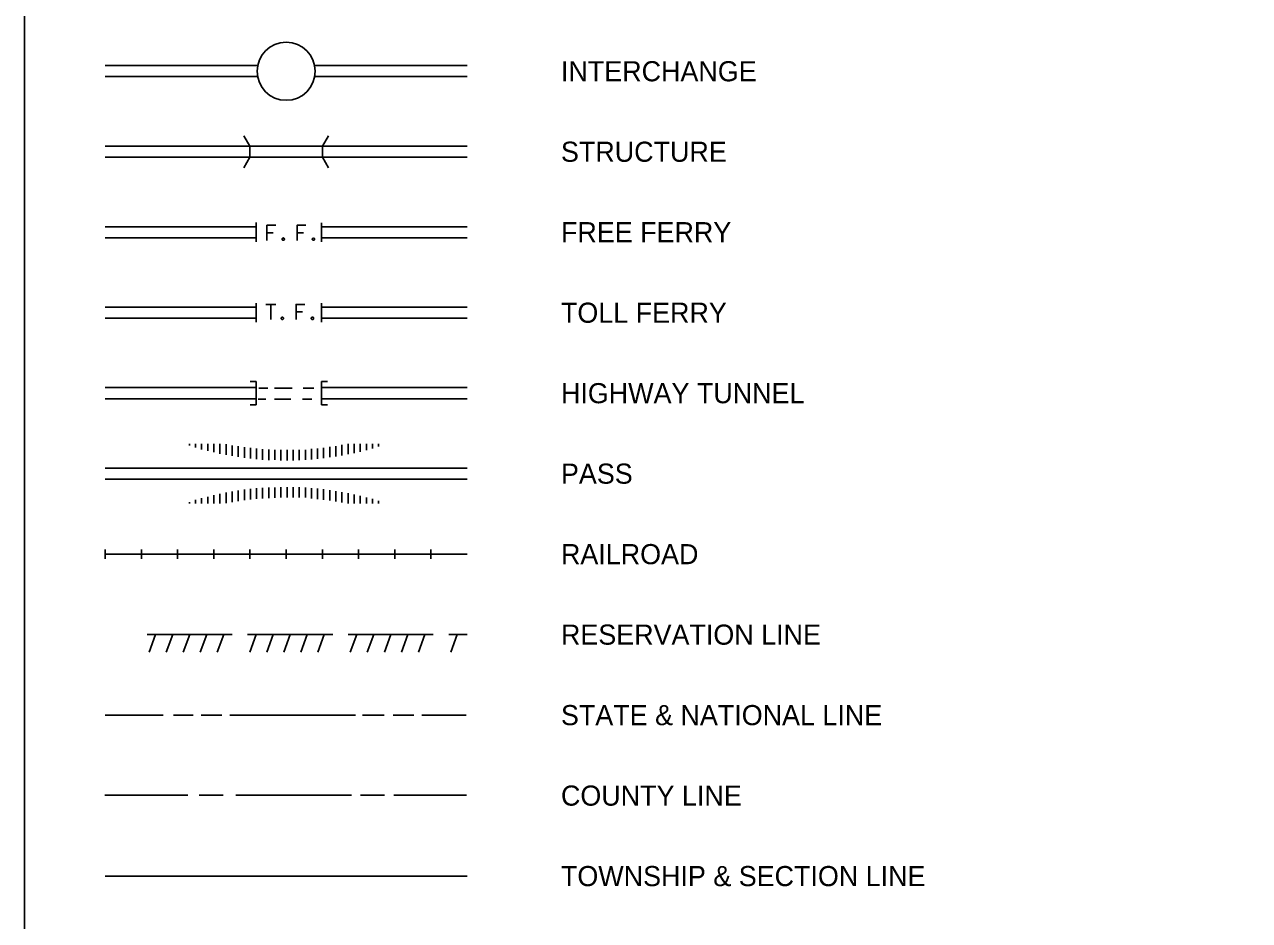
# Model space of a CAD drawing. Extents: x 49991.4 to 50021, y 49987.6 to 50011.4.
# Drawn here: x 49999.384 to 50003.039, y 49993.483 to 49996.155 of the extents above; entities that cross this region are included whole.
import ezdxf

# ---------------------------------------------------------------- set-up
doc = ezdxf.new("R2010")
doc.units = 0
doc.layers.add('Level 1', color=7, linetype='Continuous')
doc.layers.add('Level 2', color=7, linetype='Continuous')

msp = doc.modelspace()

# ---------------------------------------------------------------- linework, layer by layer
at = {"layer": 'Level 1'}
for p, q in [((49999.6243, 49996.0324), (50000.0793, 49996.0324)), ((50000.249, 49996.0324), (50000.7043, 49996.0324)), ((49999.6243, 49995.9994), (50000.0788, 49995.9994)), ((50000.2495, 49995.9994), (50000.7043, 49995.9994)), ((50000.0563, 49995.7917), (50000.0383, 49995.8228)), ((50000.2723, 49995.7917), (50000.2903, 49995.8228)), ((49999.6243, 49995.7917), (50000.7043, 49995.7917)), ((50000.0563, 49995.7917), (50000.0563, 49995.7587)), ((50000.2723, 49995.7917), (50000.2723, 49995.7587)), ((49999.6243, 49995.7587), (50000.7043, 49995.7587)), ((50000.0563, 49995.7587), (50000.0383, 49995.7275)), ((50000.2723, 49995.7587), (50000.2903, 49995.7275)), ((49999.6243, 49995.5517), (50000.0745, 49995.5517)), ((50000.0744, 49995.5067), (50000.0744, 49995.564)), ((50000.2697, 49995.5067), (50000.2697, 49995.5636)), ((50000.2698, 49995.5517), (50000.7043, 49995.5517)), ((49999.6243, 49995.5187), (50000.0745, 49995.5187)), ((50000.1075, 49995.5335), (50000.1259, 49995.5335)), ((50000.1523, 49995.5152), (50000.1522, 49995.5148)), ((50000.1522, 49995.5148), (50000.1522, 49995.5145)), ((50000.1522, 49995.5145), (50000.1522, 49995.5141)), ((50000.1522, 49995.5141), (50000.1523, 49995.5137)), ((50000.1524, 49995.5156), (50000.1523, 49995.5152)), ((50000.1523, 49995.5137), (50000.1524, 49995.5134)), ((50000.1525, 49995.5159), (50000.1524, 49995.5156)), ((50000.1524, 49995.5134), (50000.1525, 49995.513)), ((50000.1527, 49995.5162), (50000.1525, 49995.5159)), ((50000.1525, 49995.513), (50000.1527, 49995.5127)), ((50000.1529, 49995.5166), (50000.1527, 49995.5162)), ((50000.1527, 49995.5127), (50000.1529, 49995.5124)), ((50000.1531, 49995.5168), (50000.1529, 49995.5166)), ((50000.1529, 49995.5124), (50000.1531, 49995.5121)), ((50000.1534, 49995.5171), (50000.1531, 49995.5168)), ((50000.1531, 49995.5121), (50000.1534, 49995.5118)), ((50000.1536, 49995.5173), (50000.1534, 49995.5171)), ((50000.1534, 49995.5118), (50000.1536, 49995.5116)), ((50000.154, 49995.5175), (50000.1536, 49995.5173)), ((50000.1536, 49995.5116), (50000.154, 49995.5114)), ((50000.1543, 49995.5177), (50000.154, 49995.5175)), ((50000.154, 49995.5114), (50000.1543, 49995.5112)), ((50000.1546, 49995.5178), (50000.1543, 49995.5177)), ((50000.1543, 49995.5112), (50000.1546, 49995.5111)), ((50000.155, 49995.5179), (50000.1546, 49995.5178)), ((50000.1546, 49995.5111), (50000.155, 49995.511)), ((50000.1554, 49995.518), (50000.155, 49995.5179)), ((50000.155, 49995.511), (50000.1554, 49995.511)), ((50000.1557, 49995.518), (50000.1554, 49995.518)), ((50000.1554, 49995.511), (50000.1557, 49995.5109)), ((50000.1561, 49995.518), (50000.1557, 49995.518)), ((50000.1557, 49995.5109), (50000.1561, 49995.511)), ((50000.1565, 49995.5179), (50000.1561, 49995.518)), ((50000.1561, 49995.511), (50000.1565, 49995.511)), ((50000.1568, 49995.5178), (50000.1565, 49995.5179)), ((50000.1565, 49995.511), (50000.1568, 49995.5111)), ((50000.1572, 49995.5177), (50000.1568, 49995.5178)), ((50000.1568, 49995.5111), (50000.1572, 49995.5112)), ((50000.1575, 49995.5175), (50000.1572, 49995.5177)), ((50000.1572, 49995.5112), (50000.1575, 49995.5114)), ((50000.1578, 49995.5173), (50000.1575, 49995.5175)), ((50000.1575, 49995.5114), (50000.1578, 49995.5116)), ((50000.1581, 49995.5171), (50000.1578, 49995.5173)), ((50000.1578, 49995.5116), (50000.1581, 49995.5118)), ((50000.1584, 49995.5168), (50000.1581, 49995.5171)), ((50000.1581, 49995.5118), (50000.1584, 49995.5121)), ((50000.1586, 49995.5166), (50000.1584, 49995.5168)), ((50000.1584, 49995.5121), (50000.1586, 49995.5124)), ((50000.1588, 49995.5162), (50000.1586, 49995.5166)), ((50000.1586, 49995.5124), (50000.1588, 49995.5127)), ((50000.159, 49995.5159), (50000.1588, 49995.5162)), ((50000.1588, 49995.5127), (50000.159, 49995.513)), ((50000.1591, 49995.5156), (50000.159, 49995.5159)), ((50000.159, 49995.513), (50000.1591, 49995.5134)), ((50000.1592, 49995.5152), (50000.1591, 49995.5156)), ((50000.1591, 49995.5134), (50000.1592, 49995.5137)), ((50000.1593, 49995.5148), (50000.1592, 49995.5152)), ((50000.1592, 49995.5137), (50000.1593, 49995.5141)), ((50000.1593, 49995.5145), (50000.1593, 49995.5148)), ((50000.1593, 49995.5141), (50000.1593, 49995.5145)), ((50000.1975, 49995.5335), (50000.2159, 49995.5335)), ((50000.2423, 49995.5152), (50000.2422, 49995.5148)), ((50000.2422, 49995.5148), (50000.2422, 49995.5145)), ((50000.2422, 49995.5145), (50000.2422, 49995.5141)), ((50000.2422, 49995.5141), (50000.2423, 49995.5137)), ((50000.2424, 49995.5156), (50000.2423, 49995.5152)), ((50000.2423, 49995.5137), (50000.2424, 49995.5134)), ((50000.2425, 49995.5159), (50000.2424, 49995.5156)), ((50000.2424, 49995.5134), (50000.2425, 49995.513)), ((50000.2427, 49995.5162), (50000.2425, 49995.5159)), ((50000.2425, 49995.513), (50000.2427, 49995.5127)), ((50000.2429, 49995.5166), (50000.2427, 49995.5162)), ((50000.2427, 49995.5127), (50000.2429, 49995.5124)), ((50000.2431, 49995.5168), (50000.2429, 49995.5166)), ((50000.2429, 49995.5124), (50000.2431, 49995.5121)), ((50000.2434, 49995.5171), (50000.2431, 49995.5168)), ((50000.2431, 49995.5121), (50000.2434, 49995.5118)), ((50000.2436, 49995.5173), (50000.2434, 49995.5171)), ((50000.2434, 49995.5118), (50000.2436, 49995.5116)), ((50000.244, 49995.5175), (50000.2436, 49995.5173)), ((50000.2436, 49995.5116), (50000.244, 49995.5114)), ((50000.2443, 49995.5177), (50000.244, 49995.5175)), ((50000.244, 49995.5114), (50000.2443, 49995.5112)), ((50000.2446, 49995.5178), (50000.2443, 49995.5177)), ((50000.2443, 49995.5112), (50000.2446, 49995.5111)), ((50000.245, 49995.5179), (50000.2446, 49995.5178)), ((50000.2446, 49995.5111), (50000.245, 49995.511)), ((50000.2454, 49995.518), (50000.245, 49995.5179)), ((50000.245, 49995.511), (50000.2454, 49995.511)), ((50000.2457, 49995.518), (50000.2454, 49995.518)), ((50000.2454, 49995.511), (50000.2457, 49995.5109)), ((50000.2461, 49995.518), (50000.2457, 49995.518)), ((50000.2457, 49995.5109), (50000.2461, 49995.511)), ((50000.2465, 49995.5179), (50000.2461, 49995.518)), ((50000.2461, 49995.511), (50000.2465, 49995.511)), ((50000.2468, 49995.5178), (50000.2465, 49995.5179)), ((50000.2465, 49995.511), (50000.2468, 49995.5111)), ((50000.2472, 49995.5177), (50000.2468, 49995.5178)), ((50000.2468, 49995.5111), (50000.2472, 49995.5112)), ((50000.2475, 49995.5175), (50000.2472, 49995.5177)), ((50000.2472, 49995.5112), (50000.2475, 49995.5114)), ((50000.2478, 49995.5173), (50000.2475, 49995.5175)), ((50000.2475, 49995.5114), (50000.2478, 49995.5116)), ((50000.2481, 49995.5171), (50000.2478, 49995.5173)), ((50000.2478, 49995.5116), (50000.2481, 49995.5118)), ((50000.2484, 49995.5168), (50000.2481, 49995.5171)), ((50000.2481, 49995.5118), (50000.2484, 49995.5121)), ((50000.2486, 49995.5166), (50000.2484, 49995.5168)), ((50000.2484, 49995.5121), (50000.2486, 49995.5124)), ((50000.2488, 49995.5162), (50000.2486, 49995.5166)), ((50000.2486, 49995.5124), (50000.2488, 49995.5127)), ((50000.249, 49995.5159), (50000.2488, 49995.5162)), ((50000.2488, 49995.5127), (50000.249, 49995.513)), ((50000.2491, 49995.5156), (50000.249, 49995.5159)), ((50000.249, 49995.513), (50000.2491, 49995.5134)), ((50000.2492, 49995.5152), (50000.2491, 49995.5156)), ((50000.2491, 49995.5134), (50000.2492, 49995.5137)), ((50000.2493, 49995.5148), (50000.2492, 49995.5152)), ((50000.2492, 49995.5137), (50000.2493, 49995.5141)), ((50000.2493, 49995.5145), (50000.2493, 49995.5148)), ((50000.2493, 49995.5141), (50000.2493, 49995.5145)), ((50000.27, 49995.5187), (50000.7043, 49995.5187)), ((50000.0743, 49995.3237), (50000.0743, 49995.267)), ((50000.27, 49995.3237), (50000.27, 49995.2667)), ((49999.6243, 49995.3117), (50000.0745, 49995.3117)), ((50000.1041, 49995.3197), (50000.1335, 49995.3197)), ((50000.119, 49995.3197), (50000.119, 49995.2747)), ((50000.1945, 49995.2974), (50000.2129, 49995.2974)), ((50000.27, 49995.3117), (50000.7043, 49995.3117)), ((49999.6243, 49995.2787), (50000.0745, 49995.2787)), ((50000.1493, 49995.2791), (50000.1492, 49995.2787)), ((50000.1492, 49995.2787), (50000.1492, 49995.2784)), ((50000.1492, 49995.2784), (50000.1492, 49995.278)), ((50000.1492, 49995.278), (50000.1493, 49995.2776)), ((50000.1494, 49995.2795), (50000.1493, 49995.2791)), ((50000.1493, 49995.2776), (50000.1494, 49995.2773)), ((50000.1495, 49995.2798), (50000.1494, 49995.2795)), ((50000.1494, 49995.2773), (50000.1495, 49995.2769)), ((50000.1497, 49995.2801), (50000.1495, 49995.2798)), ((50000.1495, 49995.2769), (50000.1497, 49995.2766)), ((50000.1499, 49995.2805), (50000.1497, 49995.2801)), ((50000.1497, 49995.2766), (50000.1499, 49995.2763)), ((50000.1501, 49995.2807), (50000.1499, 49995.2805)), ((50000.1499, 49995.2763), (50000.1501, 49995.276)), ((50000.1504, 49995.281), (50000.1501, 49995.2807)), ((50000.1501, 49995.276), (50000.1504, 49995.2757)), ((50000.1506, 49995.2812), (50000.1504, 49995.281)), ((50000.1504, 49995.2757), (50000.1506, 49995.2755)), ((50000.151, 49995.2814), (50000.1506, 49995.2812)), ((50000.1506, 49995.2755), (50000.151, 49995.2753)), ((50000.1513, 49995.2816), (50000.151, 49995.2814)), ((50000.151, 49995.2753), (50000.1513, 49995.2751)), ((50000.1516, 49995.2817), (50000.1513, 49995.2816)), ((50000.1513, 49995.2751), (50000.1516, 49995.275)), ((50000.152, 49995.2818), (50000.1516, 49995.2817)), ((50000.1516, 49995.275), (50000.152, 49995.2749)), ((50000.1524, 49995.2819), (50000.152, 49995.2818)), ((50000.152, 49995.2749), (50000.1524, 49995.2749)), ((50000.1527, 49995.2819), (50000.1524, 49995.2819)), ((50000.1524, 49995.2749), (50000.1527, 49995.2748)), ((50000.1531, 49995.2819), (50000.1527, 49995.2819)), ((50000.1527, 49995.2748), (50000.1531, 49995.2749)), ((50000.1535, 49995.2818), (50000.1531, 49995.2819)), ((50000.1531, 49995.2749), (50000.1535, 49995.2749)), ((50000.1538, 49995.2817), (50000.1535, 49995.2818)), ((50000.1535, 49995.2749), (50000.1538, 49995.275)), ((50000.1542, 49995.2816), (50000.1538, 49995.2817)), ((50000.1538, 49995.275), (50000.1542, 49995.2751)), ((50000.1545, 49995.2814), (50000.1542, 49995.2816)), ((50000.1542, 49995.2751), (50000.1545, 49995.2753)), ((50000.1548, 49995.2812), (50000.1545, 49995.2814)), ((50000.1545, 49995.2753), (50000.1548, 49995.2755)), ((50000.1551, 49995.281), (50000.1548, 49995.2812)), ((50000.1548, 49995.2755), (50000.1551, 49995.2757)), ((50000.1554, 49995.2807), (50000.1551, 49995.281)), ((50000.1551, 49995.2757), (50000.1554, 49995.276)), ((50000.1556, 49995.2805), (50000.1554, 49995.2807)), ((50000.1554, 49995.276), (50000.1556, 49995.2763)), ((50000.1558, 49995.2801), (50000.1556, 49995.2805)), ((50000.1556, 49995.2763), (50000.1558, 49995.2766)), ((50000.156, 49995.2798), (50000.1558, 49995.2801)), ((50000.1558, 49995.2766), (50000.156, 49995.2769)), ((50000.1561, 49995.2795), (50000.156, 49995.2798)), ((50000.156, 49995.2769), (50000.1561, 49995.2773)), ((50000.1562, 49995.2791), (50000.1561, 49995.2795)), ((50000.1561, 49995.2773), (50000.1562, 49995.2776)), ((50000.1563, 49995.2787), (50000.1562, 49995.2791)), ((50000.1562, 49995.2776), (50000.1563, 49995.278)), ((50000.1563, 49995.2784), (50000.1563, 49995.2787)), ((50000.1563, 49995.278), (50000.1563, 49995.2784)), ((50000.2393, 49995.2791), (50000.2392, 49995.2787)), ((50000.2392, 49995.2787), (50000.2392, 49995.2784)), ((50000.2392, 49995.2784), (50000.2392, 49995.278)), ((50000.2392, 49995.278), (50000.2393, 49995.2776)), ((50000.2394, 49995.2795), (50000.2393, 49995.2791)), ((50000.2393, 49995.2776), (50000.2394, 49995.2773)), ((50000.2395, 49995.2798), (50000.2394, 49995.2795)), ((50000.2394, 49995.2773), (50000.2395, 49995.2769)), ((50000.2397, 49995.2801), (50000.2395, 49995.2798)), ((50000.2395, 49995.2769), (50000.2397, 49995.2766)), ((50000.2399, 49995.2805), (50000.2397, 49995.2801)), ((50000.2397, 49995.2766), (50000.2399, 49995.2763)), ((50000.2401, 49995.2807), (50000.2399, 49995.2805)), ((50000.2399, 49995.2763), (50000.2401, 49995.276)), ((50000.2404, 49995.281), (50000.2401, 49995.2807)), ((50000.2401, 49995.276), (50000.2404, 49995.2757)), ((50000.2406, 49995.2812), (50000.2404, 49995.281)), ((50000.2404, 49995.2757), (50000.2406, 49995.2755)), ((50000.241, 49995.2814), (50000.2406, 49995.2812)), ((50000.2406, 49995.2755), (50000.241, 49995.2753)), ((50000.2413, 49995.2816), (50000.241, 49995.2814)), ((50000.241, 49995.2753), (50000.2413, 49995.2751)), ((50000.2416, 49995.2817), (50000.2413, 49995.2816)), ((50000.2413, 49995.2751), (50000.2416, 49995.275)), ((50000.242, 49995.2818), (50000.2416, 49995.2817)), ((50000.2416, 49995.275), (50000.242, 49995.2749)), ((50000.2424, 49995.2819), (50000.242, 49995.2818)), ((50000.242, 49995.2749), (50000.2424, 49995.2749)), ((50000.2427, 49995.2819), (50000.2424, 49995.2819)), ((50000.2424, 49995.2749), (50000.2427, 49995.2748)), ((50000.2431, 49995.2819), (50000.2427, 49995.2819)), ((50000.2427, 49995.2748), (50000.2431, 49995.2749)), ((50000.2435, 49995.2818), (50000.2431, 49995.2819)), ((50000.2431, 49995.2749), (50000.2435, 49995.2749)), ((50000.2438, 49995.2817), (50000.2435, 49995.2818)), ((50000.2435, 49995.2749), (50000.2438, 49995.275)), ((50000.2442, 49995.2816), (50000.2438, 49995.2817)), ((50000.2438, 49995.275), (50000.2442, 49995.2751)), ((50000.2445, 49995.2814), (50000.2442, 49995.2816)), ((50000.2442, 49995.2751), (50000.2445, 49995.2753)), ((50000.2448, 49995.2812), (50000.2445, 49995.2814)), ((50000.2445, 49995.2753), (50000.2448, 49995.2755)), ((50000.2451, 49995.281), (50000.2448, 49995.2812)), ((50000.2448, 49995.2755), (50000.2451, 49995.2757)), ((50000.2454, 49995.2807), (50000.2451, 49995.281)), ((50000.2451, 49995.2757), (50000.2454, 49995.276)), ((50000.2456, 49995.2805), (50000.2454, 49995.2807)), ((50000.2454, 49995.276), (50000.2456, 49995.2763)), ((50000.2458, 49995.2801), (50000.2456, 49995.2805)), ((50000.2456, 49995.2763), (50000.2458, 49995.2766)), ((50000.246, 49995.2798), (50000.2458, 49995.2801)), ((50000.2458, 49995.2766), (50000.246, 49995.2769)), ((50000.2461, 49995.2795), (50000.246, 49995.2798)), ((50000.246, 49995.2769), (50000.2461, 49995.2773)), ((50000.2462, 49995.2791), (50000.2461, 49995.2795)), ((50000.2461, 49995.2773), (50000.2462, 49995.2776)), ((50000.2463, 49995.2787), (50000.2462, 49995.2791)), ((50000.2462, 49995.2776), (50000.2463, 49995.278)), ((50000.2463, 49995.2784), (50000.2463, 49995.2787)), ((50000.2463, 49995.278), (50000.2463, 49995.2784)), ((50000.27, 49995.2787), (50000.7043, 49995.2787)), ((49999.6243, 49995.0717), (50000.0744, 49995.0717)), ((50000.0744, 49995.0897), (50000.0564, 49995.0897)), ((50000.0744, 49995.0207), (50000.0744, 49995.0897)), ((50000.0824, 49995.0701), (50000.1098, 49995.0701)), ((50000.1294, 49995.0701), (50000.1822, 49995.0701)), ((50000.2154, 49995.0701), (50000.2467, 49995.0701)), ((50000.27, 49995.0717), (50000.7043, 49995.0717)), ((50000.2701, 49995.0207), (50000.2701, 49995.0897)), ((50000.2701, 49995.0897), (50000.2881, 49995.0897)), ((49999.6243, 49995.0387), (50000.0744, 49995.0387)), ((50000.0805, 49995.037), (50000.104, 49995.037)), ((50000.1294, 49995.037), (50000.1783, 49995.037)), ((50000.2135, 49995.037), (50000.2408, 49995.037)), ((50000.27, 49995.0387), (50000.7043, 49995.0387)), ((50000.0744, 49995.0207), (50000.0564, 49995.0207)), ((50000.2701, 49995.0207), (50000.2881, 49995.0207)), ((49999.8756, 49994.904), (49999.8756, 49994.8992)), ((49999.8938, 49994.904), (49999.8938, 49994.8931)), ((49999.912, 49994.904), (49999.912, 49994.8877)), ((49999.9302, 49994.904), (49999.9302, 49994.8833)), ((49999.9484, 49994.904), (49999.9484, 49994.8788)), ((49999.9666, 49994.904), (49999.9666, 49994.8745)), ((49999.9849, 49994.903), (49999.9849, 49994.871)), ((50000.0031, 49994.8995), (50000.0031, 49994.868)), ((50000.0213, 49994.897), (50000.0213, 49994.865)), ((50000.0395, 49994.8942), (50000.0395, 49994.8622)), ((50000.0577, 49994.8921), (50000.0577, 49994.8603)), ((50000.0759, 49994.89), (50000.0759, 49994.8584)), ((50000.0941, 49994.8886), (50000.0941, 49994.8568)), ((50000.1123, 49994.8874), (50000.1123, 49994.8556)), ((50000.1305, 49994.8863), (50000.1305, 49994.856)), ((50000.1487, 49994.886), (50000.1487, 49994.8545)), ((50000.1669, 49994.886), (50000.1669, 49994.8545)), ((50000.1669, 49994.8854), (50000.1669, 49994.868)), ((50000.1851, 49994.886), (50000.1851, 49994.8547)), ((50000.2034, 49994.886), (50000.2034, 49994.8553)), ((50000.2216, 49994.886), (50000.2216, 49994.8562)), ((50000.2398, 49994.8888), (50000.2398, 49994.8576)), ((50000.258, 49994.8904), (50000.258, 49994.8593)), ((50000.2762, 49994.8923), (50000.2762, 49994.8611)), ((50000.2944, 49994.8949), (50000.2944, 49994.8639)), ((50000.3126, 49994.8974), (50000.3126, 49994.8666)), ((50000.3308, 49994.9007), (50000.3308, 49994.8693)), ((50000.349, 49994.9037), (50000.349, 49994.8729)), ((50000.3672, 49994.904), (50000.3672, 49994.8766)), ((50000.3854, 49994.904), (50000.3854, 49994.8807)), ((50000.4036, 49994.904), (50000.4036, 49994.8856)), ((50000.4218, 49994.904), (50000.4218, 49994.8901)), ((50000.44, 49994.904), (50000.44, 49994.8958)), ((49999.6243, 49994.8317), (50000.7043, 49994.8317)), ((49999.6243, 49994.7987), (50000.7043, 49994.7987)), ((50000.1487, 49994.7439), (50000.1487, 49994.7753)), ((50000.1669, 49994.7439), (50000.1669, 49994.7753)), ((50000.1851, 49994.7439), (50000.1851, 49994.7752)), ((50000.2034, 49994.7439), (50000.2034, 49994.7746)), ((49999.912, 49994.7258), (49999.912, 49994.7422)), ((49999.9302, 49994.7258), (49999.9302, 49994.7465)), ((49999.9484, 49994.7258), (49999.9484, 49994.7511)), ((49999.9666, 49994.7258), (49999.9666, 49994.7554)), ((49999.9849, 49994.7269), (49999.9849, 49994.7589)), ((50000.0031, 49994.7303), (50000.0031, 49994.7618)), ((50000.0213, 49994.7329), (50000.0213, 49994.7649)), ((50000.0395, 49994.7357), (50000.0395, 49994.7676)), ((50000.0577, 49994.7378), (50000.0577, 49994.7696)), ((50000.0759, 49994.7398), (50000.0759, 49994.7715)), ((50000.0941, 49994.7412), (50000.0941, 49994.7731)), ((50000.1123, 49994.7424), (50000.1123, 49994.7742)), ((50000.1305, 49994.7436), (50000.1305, 49994.7739)), ((50000.1669, 49994.7445), (50000.1669, 49994.7618)), ((50000.2216, 49994.7439), (50000.2216, 49994.7736)), ((50000.2398, 49994.741), (50000.2398, 49994.7723)), ((50000.258, 49994.7395), (50000.258, 49994.7705)), ((50000.2762, 49994.7375), (50000.2762, 49994.7688)), ((50000.2944, 49994.735), (50000.2944, 49994.766)), ((50000.3126, 49994.7324), (50000.3126, 49994.7633)), ((50000.3308, 49994.7292), (50000.3308, 49994.7605)), ((50000.349, 49994.7262), (50000.349, 49994.7569)), ((50000.3672, 49994.7258), (50000.3672, 49994.7532)), ((50000.3854, 49994.7258), (50000.3854, 49994.7492)), ((50000.4036, 49994.7258), (50000.4036, 49994.7443)), ((50000.4218, 49994.7258), (50000.4218, 49994.7397)), ((49999.8756, 49994.7258), (49999.8756, 49994.7306)), ((49999.8938, 49994.7258), (49999.8938, 49994.7367)), ((50000.44, 49994.7258), (50000.44, 49994.7341)), ((49999.6243, 49994.5887), (49999.6243, 49994.5617)), ((49999.6243, 49994.5752), (50000.7043, 49994.5752)), ((49999.7323, 49994.5887), (49999.7323, 49994.5617)), ((49999.8403, 49994.5887), (49999.8403, 49994.5617)), ((49999.9483, 49994.5887), (49999.9483, 49994.5617)), ((50000.0563, 49994.5887), (50000.0563, 49994.5617)), ((50000.1643, 49994.5887), (50000.1643, 49994.5617)), ((50000.2723, 49994.5887), (50000.2723, 49994.5617)), ((50000.3803, 49994.5887), (50000.3803, 49994.5617)), ((50000.4883, 49994.5887), (50000.4883, 49994.5617)), ((50000.5963, 49994.5887), (50000.5963, 49994.5617)), ((50000.7042, 49994.5752), (50000.7043, 49994.5752)), ((49999.7493, 49994.3352), (50000.0033, 49994.3352)), ((49999.7557, 49994.2827), (49999.7749, 49994.3352)), ((49999.8065, 49994.2827), (49999.8257, 49994.3352)), ((49999.8573, 49994.2827), (49999.8765, 49994.3352)), ((49999.859, 49994.3352), (49999.859, 49994.3352)), ((49999.8844, 49994.3352), (49999.8844, 49994.3352)), ((49999.9081, 49994.2827), (49999.9273, 49994.3352)), ((49999.9589, 49994.2827), (49999.9781, 49994.3352)), ((50000.0493, 49994.3352), (50000.3033, 49994.3352)), ((50000.0557, 49994.2827), (50000.0749, 49994.3352)), ((50000.1065, 49994.2827), (50000.1257, 49994.3352)), ((50000.1573, 49994.2827), (50000.1765, 49994.3352)), ((50000.159, 49994.3352), (50000.159, 49994.3352)), ((50000.1844, 49994.3352), (50000.1844, 49994.3352)), ((50000.2081, 49994.2827), (50000.2273, 49994.3352)), ((50000.2589, 49994.2827), (50000.2781, 49994.3352)), ((50000.3493, 49994.3352), (50000.6033, 49994.3352)), ((50000.3557, 49994.2827), (50000.3749, 49994.3352)), ((50000.4065, 49994.2827), (50000.4257, 49994.3352)), ((50000.4573, 49994.2827), (50000.4765, 49994.3352)), ((50000.459, 49994.3352), (50000.459, 49994.3352)), ((50000.4844, 49994.3352), (50000.4844, 49994.3352)), ((50000.5081, 49994.2827), (50000.5273, 49994.3352)), ((50000.5589, 49994.2827), (50000.5781, 49994.3352)), ((50000.6493, 49994.3352), (50000.7043, 49994.3352)), ((50000.6557, 49994.2827), (50000.6749, 49994.3352)), ((49999.6243, 49994.0952), (49999.7977, 49994.0952)), ((49999.8285, 49994.0952), (49999.8865, 49994.0952)), ((49999.9104, 49994.0952), (49999.9719, 49994.0952)), ((49999.9958, 49994.0952), (50000.3714, 49994.0952)), ((50000.3918, 49994.0952), (50000.4567, 49994.0952)), ((50000.484, 49994.0952), (50000.5455, 49994.0952)), ((50000.5694, 49994.0952), (50000.7013, 49994.0952)), ((49999.6228, 49993.8561), (49999.8709, 49993.8561)), ((49999.905, 49993.8561), (49999.9768, 49993.8561)), ((50000.0143, 49993.8561), (50000.3591, 49993.8561)), ((50000.3865, 49993.8561), (50000.4582, 49993.8561)), ((50000.4855, 49993.8561), (50000.7028, 49993.8561)), ((49999.6243, 49993.6152), (50000.7043, 49993.6152))]:
    msp.add_line(p, q, dxfattribs=at)
msp.add_lwpolyline([(49999.3835, 49998.9992), (50016.7501, 49998.9992), (50016.7501, 49987.7988), (49999.3835, 49987.7988)], close=True, dxfattribs=at)
for points in [[(50000.133, 49995.5558), (50000.1071, 49995.5558), (50000.1071, 49995.5108)], [(50000.223, 49995.5558), (50000.1971, 49995.5558), (50000.1971, 49995.5108)], [(50000.22, 49995.3197), (50000.1941, 49995.3197), (50000.1941, 49995.2747)]]:
    msp.add_lwpolyline(points, dxfattribs=at)
msp.add_circle((50000.1643, 49996.0152), 0.0867, dxfattribs=at)

# ---------------------------------------------------------------- texts
at = {"layer": 'Level 2'}
for s, p in [('INTERCHANGE         ', (50000.9843, 49995.9852)), ('STRUCTURE           ', (50000.9843, 49995.7452)), ('FREE FERRY          ', (50000.9843, 49995.5052)), ('TOLL FERRY          ', (50000.9843, 49995.2652)), ('HIGHWAY TUNNEL      ', (50000.9843, 49995.0252)), ('PASS                ', (50000.9843, 49994.7852)), ('RAILROAD            ', (50000.9843, 49994.5452)), ('RESERVATION LINE    ', (50000.9843, 49994.3052)), ('STATE & NATIONAL LINE    ', (50000.9843, 49994.0652)), ('COUNTY LINE         ', (50000.9843, 49993.8252)), ('TOWNSHIP & SECTION LINE  ', (50000.9843, 49993.5852))]:
    msp.add_text(s, height=0.059999, dxfattribs=at).set_placement(p)

doc.saveas('drawing.dxf')
